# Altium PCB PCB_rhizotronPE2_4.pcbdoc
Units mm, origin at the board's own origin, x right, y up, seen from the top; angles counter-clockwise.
Board outline 108.2 x 57.53 mm, 2 copper layers (Top Layer, Bottom Layer); 76 components, 109 nets, 306 pads, 195 vias.
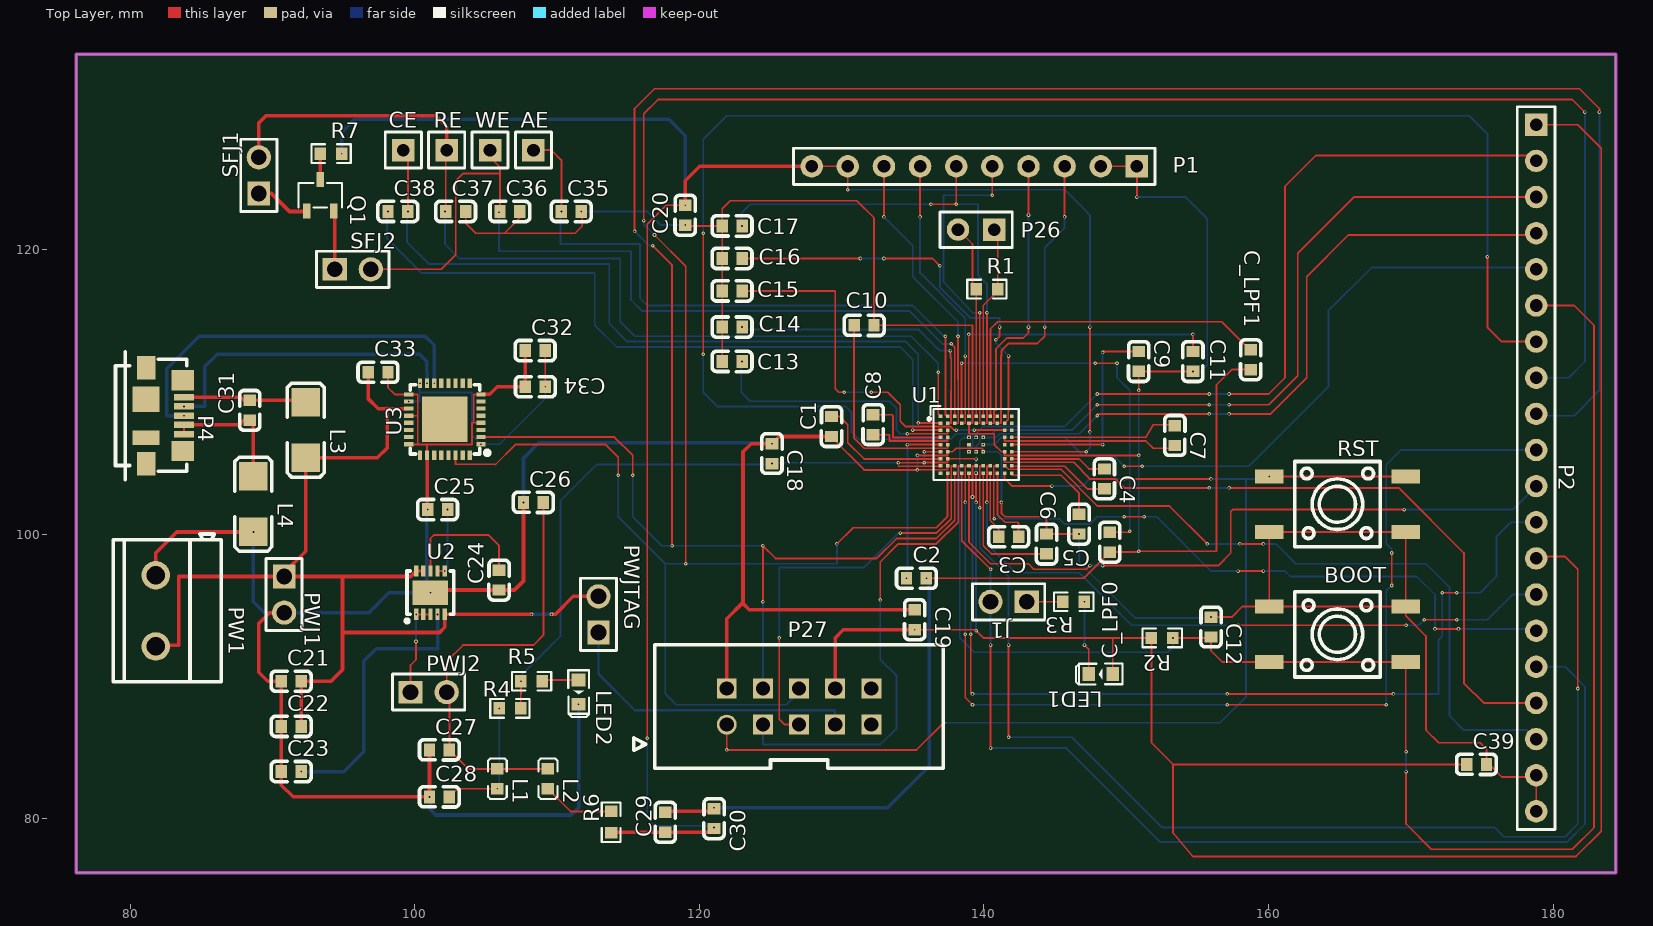
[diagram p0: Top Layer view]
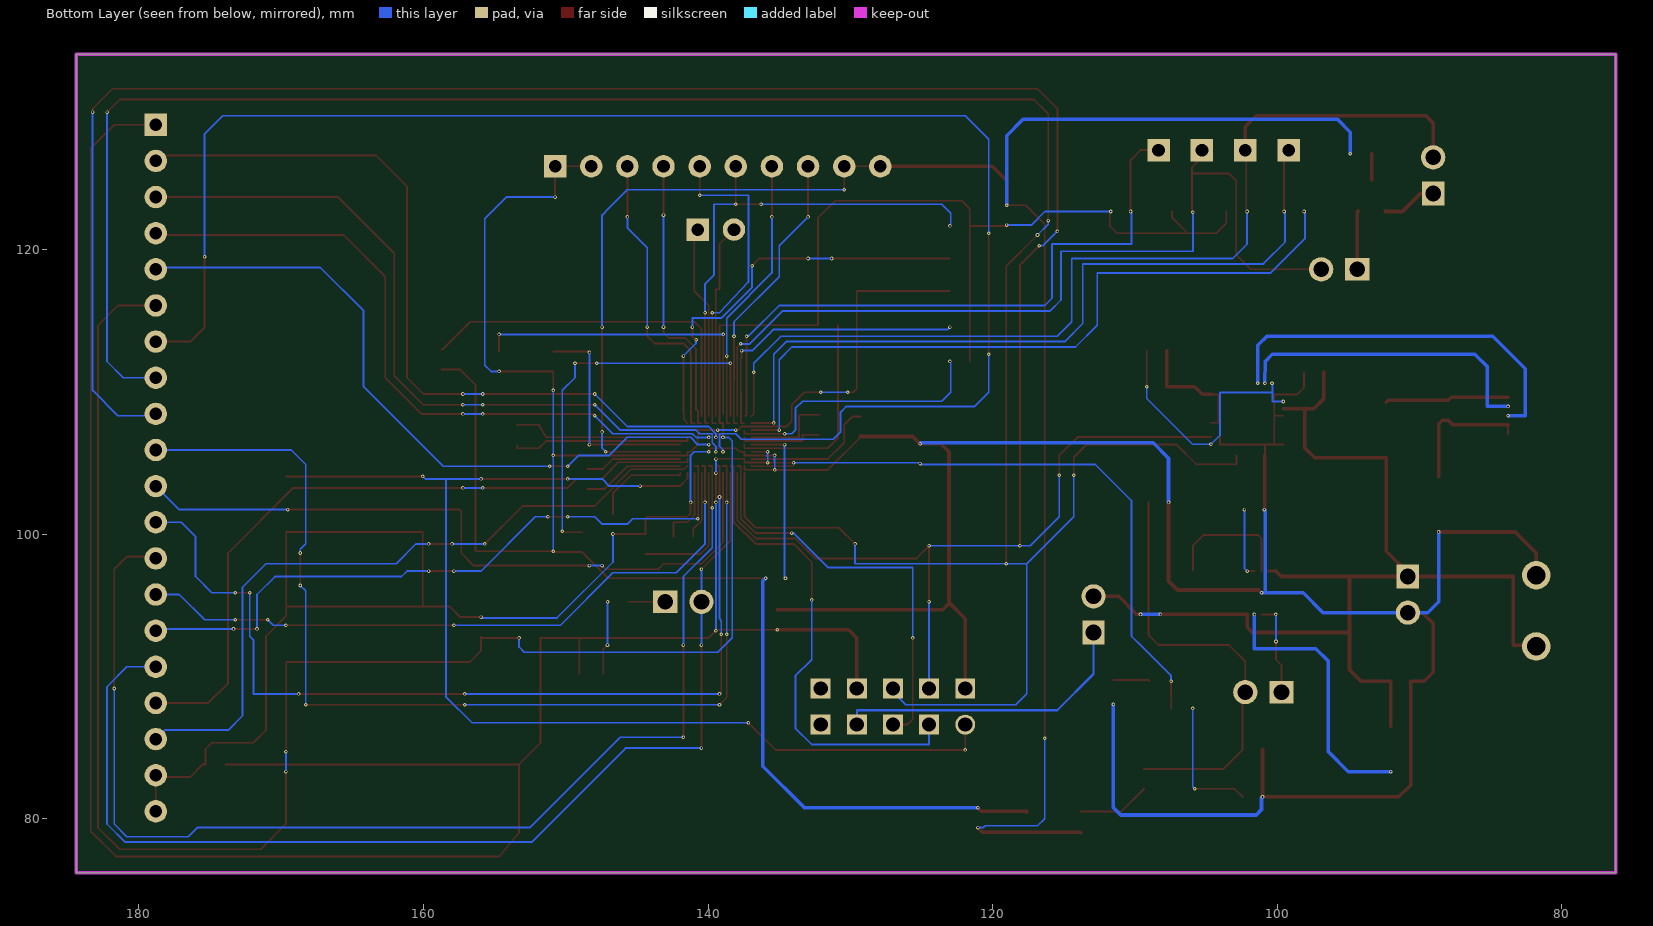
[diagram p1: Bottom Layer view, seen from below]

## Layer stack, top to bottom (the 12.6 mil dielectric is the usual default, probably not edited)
Top Layer: signal copper (thickness not stored)
Dielectric: dielectric 0.32, FR-4, Dk 4.8
Bottom Layer: signal copper (thickness not stored)

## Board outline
79.121,133.731 132.461,133.731 184.404,133.731 184.404,76.2 76.2,76.2 76.2,133.731

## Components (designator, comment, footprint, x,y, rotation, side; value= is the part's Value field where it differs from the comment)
AE "HDR-M-2.54_1x1" HDR-M-2.54_1X1 108.331,127 r270 top
BOOT "K4-6×6_SMD" KEY-SMD_4P-L6.0-W6.0-P3.90-LS10.0 164.846,92.964 r180 top
C1 "0.47uF" C0603 129.286,107.569 r90 top
C2 "0.47uF" C0603 135.255,96.901 r0 top
C3 "0.1uF" C0603 141.732,99.822 r180 top
C4 "0.1uF" C0603 148.463,103.886 r270 top
C5 "0.47uF" C0603 146.685,100.711 r90 top
C6 "0.47uF" C0603 144.399,99.314 r90 top
C7 "0.1uF" C0603 153.416,106.934 r270 top
C8 "0.1uF" C0603 132.207,107.696 r270 top
C9 "0.47uF" C0603 150.876,112.141 r90 top
C10 "0.47uF" C0603 131.572,114.681 r180 top
C11 "4.7uF" C0603 154.686,112.141 r90 top
C12 "0.1uF" C0603 155.956,93.472 r270 top
C13 "0.1uF" C0603 122.301,112.141 r0 top
C14 "0.1uF" C0603 122.301,114.554 r0 top
C15 "0.1uF" C0603 122.301,117.094 r0 top
C16 "0.1uF" C0603 122.301,119.38 r0 top
C17 "0.1uF" C0603 122.301,121.666 r0 top
C18 "0.1uF" C0603 125.095,105.664 r270 top
C19 "0.1uF" C0603 135.128,93.98 r270 top
C20 "0.1uF" C0603 118.999,122.428 r90 top
C21 "0.1uF" C0603 91.313,89.662 r0 top
C22 "10uF" C0603 91.313,86.487 r0 top
C23 "1uF" C0603 91.313,83.312 r0 top
C24 "1uF" C0603 105.918,96.774 r90 top
C25 "1uF" C0603 101.6,101.727 r0 top
C26 "10uF" C0603 108.331,102.235 r0 top
C27 "0.1uF" C0603 101.727,84.836 r0 top
C28 "0.1uF" C0603 101.727,81.534 r0 top
C29 "0.1uF" C0603 117.602,79.756 r90 top
C30 "10uF" C0603 121.031,80.01 r90 top
C31 "0.1uF" C0603 88.392,108.712 r90 top
C32 "0.1uF" C0603 108.458,112.903 r0 top
C33 "0.1uF" C0603 97.409,111.379 r0 top
C34 "0.1uF" C0603 108.458,110.363 r180 top
C35 "0.1uF" C0603 110.998,122.682 r0 top
C36 "0.1uF" C0603 106.68,122.682 r0 top
C37 "0.1uF" C0603 102.87,122.682 r0 top
C38 "0.1uF" C0603 98.806,122.682 r0 top
C39 "0.1uF" C0603 174.625,83.82 r0 top
C_LPF0 "4.7uF" C0603 148.844,99.441 r90 top
C_LPF1 "4.7uF" C0603 158.75,112.268 r90 top
CE "HDR-M-2.54_1x1" HDR-M-2.54_1X1 99.187,127 r270 top
J1 "HDR-M-2.54_1x2" HDR-M-2.54_1X2 141.732,95.25 r180 top
L1 "60Ω" L0603 105.791,82.804 r270 top
L2 "60Ω" L0603 109.347,82.804 r270 top
L3 "80Ω" L1806 92.329,107.315 r270 top
L4 "80Ω" L1806 88.646,102.108 r270 top
LED1 "LED-0603_G" LED0603_GREEN 148.209,90.17 r180 top
LED2 "LED-0603_G" LED0603_GREEN 111.506,88.9 r270 top
P1 "HDR-F-2.54_1x10" HDR-F-2.54_1X10 139.319,125.857 r180 top
P2 "HDR-F-2.54_1x20" HDR-F-2.54_1X20 178.816,104.648 r270 top
P4 "Micro B USB 2.0 SMD connector" SD-47346-001 84.455,108.331 r270 top
P26 "P26" HDR-F-2.54_1X2 139.446,121.412 r180 top
P27 "CONNMOLEX 2X5 Male" JTAG-10PIN-2.54MM-PTH 127,87.884 r0 top
PW1 "CONN-TH_2P-P5.00" CONN-TH_2P-P5.00 81.788,94.615 r270 top
PWJ1 "HDR-M-2.54_1x2" HDR-M-2.54_1X2 90.805,95.758 r270 top
PWJ2 "HDR-M-2.54_1x2" HDR-M-2.54_1X2 100.965,88.9 r0 top
PWJTAG "HDR-M-2.54_1x2" HDR-M-2.54_1X2 112.903,94.361 r90 top
Q1 "MMBFJ177" SOT-23-3_L3.0-W1.7-P0.95-LS2.9-BR 93.345,123.825 r270 top
R1 "200" R0603 140.208,117.221 r0 top
R2 "100K" R0603 152.527,92.71 r180 top
R3 "560" R0603 146.304,95.25 r180 top
R4 "2.2" R0603 106.68,87.757 r180 top
R5 "560" R0603 108.204,89.662 r180 top
R6 "2.2" R0603 113.792,79.756 r90 top
R7 "150K" R0603 94.107,126.746 r0 top
RE "HDR-M-2.54_1x1" HDR-M-2.54_1X1 102.235,127 r270 top
RST "K4-6×6_SMD" KEY-SMD_4P-L6.0-W6.0-P3.90-LS10.0 164.846,102.108 r0 top
SFJ1 "HDR-M-2.54_1x2" HDR-M-2.54_1X2 89.027,125.222 r90 top
SFJ2 "HDR-M-2.54_1x2" HDR-M-2.54_1X2 95.631,118.618 r0 top
U1 "ADUCM355BCCZ" LGA-72_L6.0-W5.0-TL_ADUCM355BCCZ-RL7 139.446,106.299 r0 top
U2 "ADP7158ACPZ-3.3-R7" LFCSP-10_L3.0-W3.0-P0.50-BL-EP 101.092,95.885 r0 top
U3 "FT232RQ" QFN-32_L5.0-W5.0-P0.50-BL-EP 102.108,108.077 r90 top
WE "HDR-M-2.54_1x1" HDR-M-2.54_1X1 105.283,127 r270 top

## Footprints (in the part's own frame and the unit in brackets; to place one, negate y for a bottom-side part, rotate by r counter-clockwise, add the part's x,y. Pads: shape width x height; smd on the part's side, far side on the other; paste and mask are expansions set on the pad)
C0603 [mm]
  rect 0.8x0.9 smd paste+0 mask+0.051: 1(-0.7,0) 2(0.7,0)
  silkscreen extent -1.41,-0.71 1.39,0.72
CONN-TH_2P-P5.00 [mm]
  round 2 hole 1.3 paste+0 mask+0.051: 1(-2.504,0) 2(2.504,0)
  silkscreen extent -5.4,-3 5,4.6
HDR-F-2.54_1X2 [mil]
  rect 62x62 hole 35 paste+0 mask+2: 1(-50,0)
  round 62 hole 35 paste+0 mask+2: 2(50,0)
  silkscreen extent -100,-49 100,50
HDR-F-2.54_1X10 [mil]
  rect 62x62 hole 35 paste+0 mask+2: 1(-450,0)
  round 62 hole 35 paste+0 mask+2: 2(-350,0) 3(-250,0) 4(-150,0) 5(-50,0) 6(50,0) 7(150,0) 8(250,0) 9(350,0) 10(450,0)
  silkscreen extent -500,-50 500,50
HDR-F-2.54_1X20 [mil]
  rect 62x62 hole 35 paste+0 mask+2: 1(-950,0)
  round 62 hole 35 paste+0 mask+2: 2(-850,0) 3(-750,0) 4(-650,0) 5(-550,0) 6(-450,0) 7(-350,0) 8(-250,0) 9(-150,0) 10(-50,0) 11(50,0) 12(150,0) 13(250,0) 14(350,0) 15(450,0) 16(550,0) 17(650,0) 18(750,0) 19(850,0) 20(950,0)
  silkscreen extent -1000,-53 1000,53
HDR-M-2.54_1X1 [mil]
  rect 62x62 hole 35 paste+0 mask+2: 1(0,0)
  silkscreen extent -50,-50 50,50
HDR-M-2.54_1X2 [mm]
  rect 1.7x1.575 hole 1.1 paste+0 mask+0.051: 1(-1.27,0)
  round 1.7 hole 1.1 paste+0 mask+0.051: 2(1.27,0)
  silkscreen extent -2.54,-1.27 2.54,1.27
JTAG-10PIN-2.54MM-PTH [mm]
  round 1.4 hole 1.001 paste+0 mask+0.051: 1(-5.08,-1.27)
  rect 1.4x1.4 hole 1.001 paste+0 mask+0.051: 2(-5.08,1.27) 3(-2.54,-1.27) 4(-2.54,1.27) 5(0,-1.27) 6(0,1.27) 7(2.54,-1.27) 8(2.54,1.27) 9(5.08,-1.27) 10(5.08,1.27)
  silkscreen extent -11.61,-4.34 10.13,4.34
KEY-SMD_4P-L6.0-W6.0-P3.90-LS10.0 [mm]
  rect 2x1 smd paste+0 mask+0.051: 1(-4.8,1.95) 2(4.8,1.95) 3(-4.8,-1.95) 4(4.8,-1.95)
  silkscreen extent -3,-3 3,3
L0603 [mm]
  rect 0.8x0.864 smd paste-100 mask+0.051: 1(-0.7,0) 2(0.7,0)
  silkscreen extent -1.42,-0.65 1.41,0.67
L1806 [mm]
  rect 2x2 smd paste+0 mask+0.051: 1(-1.95,0) 2(1.95,0)
  silkscreen extent -3.3,-1.3 3.3,1.3
LED0603_GREEN [mm]
  rect 0.9x1 smd paste+0 mask+0.051: 1(-0.85,0) 2(0.85,0)
  silkscreen extent -1.54,-0.73 1.75,0.73
LFCSP-10_L3.0-W3.0-P0.50-BL-EP [mm]
  rect 0.3x0.8 smd paste+0 mask+0.051: 1(-1,-1.524) 2(-0.5,-1.524) 3(0,-1.524) 4(0.5,-1.524) 5(1,-1.524) 6(1,1.524) 7(0.5,1.524) 8(0,1.524) 9(-0.5,1.524) 10(-1,1.524)
  rect 2.5x1.75 smd paste+0 mask+0.051: 11(0,0)
  silkscreen extent -1.77,-2.11 1.65,1.52
LGA-72_L6.0-W5.0-TL_ADUCM355BCCZ-RL7 [mm]
  rect 0.25x0.25 smd paste+0 mask+0.051: A1(-2.5,2) A2(-2,2) A3(-1.5,2) A4(-1,2) A5(-0.5,2) A6(0,2) A7(0.5,2) A8(1,2) A9(1.5,2) A10(2,2) A11(2.5,2) B1(-2.5,1.5) B2(-2,1.5) B3(-1.5,1.5) B4(-1,1.5) B5(-0.5,1.5) B6(0,1.5) B7(0.5,1.5) B8(1,1.5) B9(1.5,1.5) B10(2,1.5) B11(2.5,1.5) C1(-2.5,1) C2(-2,1) C10(2,1) C11(2.5,1) D1(-2.5,0.5) D2(-2,0.5) D5(-0.5,0.5) D6(0,0.5) D7(0.5,0.5) D10(2,0.5) D11(2.5,0.5) E1(-2.5,0) E2(-2,0) E5(-0.5,0) E7(0.5,0) E10(2,0) E11(2.5,0) F1(-2.5,-0.5) F2(-2,-0.5) F5(-0.5,-0.5) F6(0,-0.5) F7(0.5,-0.5) F10(2,-0.5) F11(2.5,-0.5) G1(-2.5,-1) G2(-2,-1) G10(2,-1) G11(2.5,-1) H1(-2.5,-1.5) H2(-2,-1.5) H3(-1.5,-1.5) H4(-1,-1.5) H5(-0.5,-1.5) H6(0,-1.5) H7(0.5,-1.5) H8(1,-1.5) H9(1.5,-1.5) H10(2,-1.5) H11(2.5,-1.5) J1(-2.5,-2) J2(-2,-2) J3(-1.5,-2) J4(-1,-2) J5(-0.5,-2) J6(0,-2) J7(0.5,-2) J8(1,-2) J9(1.5,-2) J10(2,-2) J11(2.5,-2)
  silkscreen extent -3.4,-2.5 3,2.7
QFN-32_L5.0-W5.0-P0.50-BL-EP [mil]
  rect 11.8x26 smd paste-3937 mask+1.97: 1(-68.9,-100) 2(-49.21,-100) 3(-29.53,-100) 4(-9.84,-100) 5(9.84,-100) 6(29.53,-100) 7(49.21,-100) 8(68.9,-100) 17(68.9,100) 18(49.21,100) 19(29.53,100) 20(9.84,100) 21(-9.84,100) 22(-29.53,100) 23(-49.21,100) 24(-68.9,100)
  rect 26x11.8 smd paste-3937 mask+1.97: 9(100,-68.9) 10(100,-49.21) 11(100,-29.53) 12(100,-9.84) 13(100,9.84) 14(100,29.53) 15(100,49.21) 16(100,68.9) 25(-100,68.9) 26(-100,49.21) 27(-100,29.53) 28(-100,9.84) 29(-100,-9.84) 30(-100,-29.53) 31(-100,-49.21) 32(-100,-68.9)
  rect 126x126 smd paste-3937 mask+1.97: 33(0,0)
  silkscreen extent -99,-123 96,96
R0603 [mm]
  rect 0.806x0.864 smd paste-100 mask+0.051: 1(-0.753,0) 2(0.753,0)
  silkscreen extent -1.39,-0.66 1.39,0.66
SD-47346-001 [mm]
  rect 0.45x1.38 smd paste+0 mask+0.102: 1(-1.3,-0.69) 2(-0.65,-0.69) 3(0,-0.69) 4(0.65,-0.69) 5(1.3,-0.69)
  rect 1.425x1.55 smd paste+0 mask+0.102: 6(-2.488,-0.775) GND(2.488,-0.775)
  rect 1.65x1.3 smd paste+0 mask+0.102: 7(-3.375,-3.35) 10(3.375,-3.35)
  rect 1.8x1.9 smd paste+0 mask+0.102: 8(-1.15,-3.35)
  rect 1x1.9 smd paste+0 mask+0.102: 9(1.55,-3.35)
  silkscreen extent -4.49,-5.5 4.49,-0.5
SOT-23-3_L3.0-W1.7-P0.95-LS2.9-BR [mm]
  rect 1.037x0.532 smd paste+0 mask+0.051: 1(1.101,-0.95) 2(1.101,0.95) 3(-1.101,0)
  silkscreen extent -0.86,-1.53 0.86,1.53

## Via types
v1: diameter 0.25, hole 0.125, Top Layer to Bottom Layer, tented both sides, 195 vias

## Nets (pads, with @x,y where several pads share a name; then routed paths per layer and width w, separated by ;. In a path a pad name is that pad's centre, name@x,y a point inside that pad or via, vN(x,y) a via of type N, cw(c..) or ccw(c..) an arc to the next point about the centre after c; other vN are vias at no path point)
3V3VOUT: C32.2 C34.1 U3.1 U3.16 U3.18 | length 18.8
  Top Layer w0.125: v1(109.158,110.363) C32.2
  Bottom Layer w0.125: v1(99.568,109.327) 100.33,109.327 100.33,110.589 v1(100.358,110.617) ; 100.33,109.958 104.013,109.958 104.013,106.962 v1(104.648,106.327) 105.946,106.327 109.159,109.54 v1(109.158,110.363)
5VUSB: C21.2 C22.2 C33.1 L3.2 PW1.2 PWJ1.1 PWJTAG.2 U2.5 U2.9 U2.10 U3.19 | length 79.4
  Top Layer w0.225: U2.10 U2.9
  Top Layer w0.254: PW1.2 81.879,92.202 83.403,92.202 83.403,97.028 ; 83.439,97.028 83.403,97.028 ; C22.2 C21.2 94.107,89.662 94.911,90.466 94.911,97.028 ; L3.2 97.363,105.364 98.044,106.045 98.044,108.331 98.044,108.839 U3.19 ; L3.2 92.329,98.806 90.805,97.282 PWJ1.1 ; 94.91,92.837 94.91,93.091 101.727,93.091 102.093,93.457 U2.5 ; C33.1 96.708,109.535 97.419,108.826 98.044,108.826 ; U2.10 99.711,97.028 PWJ1.1 ; U2.5 v1(108.204,94.361) ; v1(109.601,94.361) 109.855,94.361 111.125,95.631 PWJTAG.2 ; 83.403,97.028 PWJ1.1
  Bottom Layer w0.254: v1(108.204,94.361) v1(109.601,94.361)
AFEDIE_GPIO0: P2.17 U1.G10 | length 50
  Top Layer w0.125: U1.G10 141.447,105.059 146.304,105.059 147.447,103.886 149.225,103.886 149.86,103.251 v1(155.829,103.251) ; v1(157.226,103.251) 169.164,103.251 173.736,98.679 173.736,89.535 175.133,88.138 P2.17
  Bottom Layer w0.125: v1(155.829,103.251) v1(157.226,103.251)
AFEDIE_GPIO1: P2.18 U1.H10 | length 50.6
  Top Layer w0.125: U1.H10@141.447,104.798 141.724,104.561 145.415,104.561 147.955,101.981 153.035,101.981 v1(155.702,99.314) ; v1(157.988,99.314) v1(159.639,99.314)
  Bottom Layer w0.125: v1(155.702,99.314) v1(157.988,99.314) ; v1(159.639,99.314) 160.528,99.314 161.925,97.917 171.069,97.917 172.72,96.266 172.72,87.249 173.736,86.233 178.181,86.233 P2.18
AGND: C2.2 C9.1 C10.1 C11.1 C13.1 C14.1 C15.1 C16.1 C17.1 C20.1 C29.2 C30.2 C35.2 C36.2 C37.2 C_LPF0.1 C_LPF1.1 P1.1 P1.2 U1.B5 U1.F10 | length 187.6
  Top Layer w0.125: C37.2 103.57,121.855 104.267,121.158 106.299,121.158 ; C36.2 107.38,122.239 106.299,121.158 ; v1(111.698,122.682) 111.76,122.682 111.76,121.666 111.252,121.158 106.299,121.158 ; v1(118.999,121.728) 119.061,121.666 C17.1 ; C13.1 C14.1 C15.1 C16.1 C17.1 ; C10.1 132.272,122.236 131.064,123.444 122.174,123.444 121.601,122.871 C17.1 ; C10.1 139.192,114.681 139.192,111.445 139.184,107.823 U1.B5@138.938,107.823 ; v1(135.955,96.901) 147.004,96.901 C_LPF0.1 150.811,98.741 v1(150.876,98.806) 156.337,98.806 156.337,110.49 157.415,111.568 C_LPF1.1 ; U1.B5@138.946,107.8 138.946,107.061 140.716,107.061 140.716,106.299 141.232,105.799 U1.F10 141.447,105.537 v1(150.876,105.537) ; P1.2 P1.1 v1(150.749,123.698) ; 150.876,110.236 C9.1 v1(154.686,111.441)
  Top Layer w0.254: C29.2 117.602,80.518 120.777,80.518 v1(121.031,80.772)
  Bottom Layer w0.125: v1(111.698,122.682) 116.332,122.682 117.286,121.728 v1(118.999,121.728) ; v1(150.749,123.698) 154.178,123.698 155.702,122.174 155.702,111.887 155.256,111.441 v1(154.686,111.441) ; v1(150.876,98.806) v1(150.876,105.537) 150.876,110.236
  Bottom Layer w0.254: v1(121.031,80.772) 133.223,80.772 136.144,83.693 136.144,96.712 v1(135.955,96.901)
  other v1: 150.876,110.109
AIN0: P1.3 U1.B9 | length 21.3
  Top Layer w0.125: U1.B9 141.191,107.799 141.191,112.522 ; 141.224,112.522 141.224,112.903 141.732,113.411 143.764,113.411 144.272,113.919 v1(144.272,114.554) ; v1(145.669,122.301) P1.3
  Bottom Layer w0.125: v1(144.272,114.554) 144.272,120.142 145.669,121.539 v1(145.669,122.301)
AIN1: P1.4 U1.B8 | length 20.1
  Top Layer w0.125: U1.B8@140.447,107.8 140.707,107.8 140.707,108.712 140.843,108.712 140.843,112.522 140.843,113.03 141.605,113.792 142.748,113.792 143.129,114.173 v1(143.129,114.554) ; v1(143.129,122.428) P1.4
  Bottom Layer w0.125: v1(143.129,114.554) v1(143.129,122.428)
AIN2: P1.5 U1.B6 | length 23.1
  Top Layer w0.125: U1.B6@139.446,107.8 139.7,107.8 v1(139.7,115.57) ; v1(140.589,123.825) P1.5
  Bottom Layer w0.125: v1(139.7,115.57) 139.192,115.57 137.16,117.729 137.16,123.825 v1(140.589,123.825)
AIN3: C17.2 P1.6 U1.B7 | length 36.4
  Top Layer w0.125: v1(136.271,123.19) v1(138.049,123.19) P1.6 ; U1.B7 140.208,107.799 v1(140.208,115.57)
  Bottom Layer w0.125: v1(123.001,121.666) 122.936,121.666 122.936,122.555 123.571,123.19 v1(136.271,123.19) ; v1(138.049,123.19) 139.573,123.19 139.573,118.237 140.208,117.602 v1(140.208,115.57)
AIN5: P1.7 U1.B4 | length 19.6
  Top Layer w0.125: v1(135.509,122.301) P1.7 ; U1.B4@138.455,107.8 138.684,107.8 v1(138.684,112.522)
  Bottom Layer w0.125: v1(135.509,122.301) 135.509,118.364 138.684,115.189 v1(138.684,112.522)
AIN6: P1.8 U1.B3 | length 20.5
  Top Layer w0.125: v1(132.969,122.301) P1.8 ; U1.B3@137.947,107.8 138.196,107.8 v1(138.176,113.919)
  Bottom Layer w0.125: v1(132.969,122.301) 135.001,120.269 135.001,118.11 138.176,114.935 v1(138.176,113.919)
AVDD: C20.2 C29.1 C30.1 P1.9 P1.10 R6.1 R7.2 U1.F11 | length 143.8
  Top Layer w0.125: v1@116.332,85.598 116.332,121.793 117.667,123.128 v1(118.999,123.128) ; P1.10 P1.9 v1(130.429,124.206) ; U1.F11 141.953,105.791 v1(147.193,105.791) ; v1(147.447,107.188) v1(147.447,114.554)
  Top Layer w0.254: R6.1 113.845,79.056 C29.1 120.712,79.056 v1(121.031,79.375) ; v1(118.999,123.128) 118.999,124.841 120.015,125.857 P1.10
  Bottom Layer w0.125: v1(116.332,85.649) 116.332,80.01 116.84,79.502 120.523,79.502 120.65,79.375 v1(121.031,79.375) ; v1(130.429,124.206) 145.669,124.206 146.977,122.898 147.447,122.428 v1(147.447,114.554) ; v1(147.193,105.791) 147.447,106.045 v1(147.447,107.188)
  Bottom Layer w0.254: v1(94.86,126.746) 94.86,128.261 95.758,129.159 117.856,129.159 118.999,128.016 v1(118.999,123.128)
C23_2: C23.2 U2.4 | length 19.3
  Bottom Layer w0.254: v1(92.013,83.312) 94.996,83.312 96.393,84.709 96.393,91.059 97.282,91.948 101.592,91.948 v1(101.592,94.361)
C24_2: C24.2 U2.8 | length 9.2
  Top Layer w0.125: U2.8 101.092,99.695 101.346,99.949 105.156,99.949 105.918,99.187 C24.2
C25_2: C25.2 U2.6 U2.7 | length 4.9
  Top Layer w0.125: U2.7 v1(102.092,97.409)
  Bottom Layer w0.125: v1(102.092,97.409) 102.3,97.617 v1(102.3,101.727)
CAP_POT0: C38.1 U1.C1 | length 51.5
  Top Layer w0.125: v1(135.001,107.315) 136.93,107.315 U1.C1
  Bottom Layer w0.125: v1(98.106,122.682) 98.044,122.62 98.044,120.777 100.457,118.364 112.649,118.364 112.649,114.681 114.173,113.157 134.112,113.157 135.001,112.268 v1(135.001,107.315)
CAP_POT1: U1.C11
CE0: C38.2 CE.1 U1.B1 | length 54.7
  Top Layer w0.125: CE.1 99.506,126.681 v1(99.506,122.682) ; v1(135.382,107.823) 136.922,107.823 U1.B1
  Bottom Layer w0.125: v1(99.506,122.682) 99.441,122.617 99.441,120.523 100.965,118.999 113.665,118.999 113.665,114.808 114.935,113.538 134.493,113.538 135.382,112.649 v1(135.382,107.823)
CE1: U1.B11
DE0: AE.1 C35.1 U1.A2 | length 45.9
  Top Layer w0.125: AE.1 109.598,127 110.297,126.299 v1(110.297,122.682) ; v1(137.287,113.919) 137.287,108.331 U1.A2@137.414,108.331
  Bottom Layer w0.125: v1(110.297,122.682) 110.236,122.621 110.236,120.396 115.824,120.396 115.824,116.586 116.332,116.078 135.001,116.078 137.16,113.919 v1(137.287,113.919)
DE1: U1.A10
DVDD: C18.2 C19.2 C39.1 LED1.1 P2.1 P27.8 R2.2 R4.1 R5.2 U1.F1 U1.G2 U1.J6 | length 208.9
  Top Layer w0.125: R4.1 v1(107.45,89.662) ; v1(133.985,105.029) v1(135.806,105.029) ; v1(135.128,93.28) 139.384,93.28 v1(139.446,93.218) 139.954,92.71 R2.2 151.774,85.335 153.289,83.82 ; v1@135.806,105.044 137.447,105.044 U1.G2 ; v1(135.81,105.791) U1.F1@136.906,105.791 ; U1.G2 v1(139.446,105.283) ; v1(139.446,102.235) v1(139.446,104.299) ; LED1.1 149.059,92.71 ; C39.1 153.289,83.82 ; P2.1 181.737,128.778 183.388,127.127 183.388,79.121 181.61,77.343 154.686,77.343 153.289,78.994 153.289,83.82
  Top Layer w0.254: P27.8 129.54,92.71 130.11,93.28 v1(135.128,93.28)
  Bottom Layer w0.125: v1(107.45,89.662) 107.45,90.051 109.474,92.075 110.236,92.837 110.236,102.362 112.776,104.902 125.034,104.902 v1(125.095,104.964) ; v1(125.095,104.964) 125.16,105.029 v1(133.985,105.029) ; v1(135.806,105.029) v1(135.81,105.791) ; v1(139.446,93.218) v1(139.446,102.235) ; v1(139.446,104.299) v1(139.446,105.283)
GND: BOOT.3 BOOT.4 C1.1 C5.1 C6.2 C12.1 C18.1 C19.1 C21.1 C22.1 C23.1 C24.1 C25.1 C26.1 C27.1 C28.1 C32.1 C33.2 C34.2 C39.2 L4.2 LED2.2 P2.19 P2.20 P27.2 PW1.1 PWJ1.2 RST.3 RST.4 U1.F2 U1.F7 U1.H2 U2.11 U3.4 U3.8 U3.17 U3.20 U3.24 U3.26 | length 274.2
  Top Layer w0.125: C33.2 98.109,110.298 98.58,109.827 U3.17 100.203,109.827 100.203,108.326 ; U3.24 99.568,106.299 100.203,106.299 ; U3.20 100.198,108.326 100.203,106.299 ; 100.203,106.36 100.203,106.299 ; U3.26 100.858,106.299 ; 104.14,107.827 104.14,109.827 U3.8 ; U3.4 104.013,107.827 104.013,106.299 100.858,106.299 ; C1.1 129.286,106.807 131.572,104.521 v1(135.315,104.521) ; v1(135.315,104.521) 137.446,104.551 U1.H2 ; v1(135.32,105.537) 137.446,105.537 U1.F2 137.787,105.799 138.049,106.045 139.827,106.045 139.946,105.926 v1(139.946,105.799) ; v1(141.224,102.235) 141.224,101.473 141.478,101.219 144.272,101.219 144.399,101.092 C6.2 v1(146.682,100.014) C5.1 ; v1(155.956,94.172) 157.418,94.172 158.16,94.914 BOOT.4 ; C39.2 175.514,83.82 176.403,82.931 178.689,82.931 P2.19 P2.20 ; C39.2 175.326,84.902 174.882,85.344 171.958,85.344 171.069,86.233 171.069,92.837 169.647,94.259 BOOT.3 ; 100.203,106.299 100.858,106.299 ; BOOT.4 RST.3 RST.4 BOOT.3 ; BOOT.4 BOOT.3
  Top Layer w0.254: PW1.1 81.788,98.679 83.266,100.157 v1(88.646,100.158) ; C23.1 90.612,82.362 91.44,81.534 v1(101.027,81.534) ; C23.1 C22.1 C21.1 89.662,89.662 89.027,90.297 89.027,93.726 89.789,94.488 PWJ1.2 ; U3.26 100.858,101.727 v1(100.9,101.727) ; v1(101.027,81.534) C27.1 ; v1(101.092,95.885) 101.281,96.074 C24.1 106.996,96.074 107.631,96.709 v1(107.631,102.235) ; U3.8 105.255,109.827 105.791,110.363 C34.2 C32.1 ; P27.2 121.92,94.049 123.063,95.192 ; v1(125.095,106.365) 125.6,106.869 C1.1 ; v1(125.095,106.365) 123.637,106.365 123.063,105.791 123.063,95.123 123.505,94.681 C19.1
  Bottom Layer w0.125: v1(135.315,104.521) v1(135.32,105.537) ; v1(139.946,105.799) 140.962,105.799 141.224,105.537 v1(141.224,102.235) ; v1(146.682,100.014) 146.682,98.047 150.622,94.107 155.891,94.107 v1(155.956,94.172)
  Bottom Layer w0.254: v1(88.646,100.158) 88.646,95.25 89.408,94.488 PWJ1.2 96.774,94.488 98.171,95.885 v1(101.092,95.885) 100.838,95.885 100.838,101.666 v1(100.9,101.727) ; v1(101.027,81.534) 101.092,81.469 101.092,80.645 101.473,80.264 110.998,80.264 111.506,80.772 v1(111.506,88.05) ; v1(107.631,102.235) 107.631,105.345 108.712,106.426 125.034,106.426 v1(125.095,106.365)
L1_2: C28.2 L1.2 R4.2 | length 9.3
  Top Layer w0.125: C28.2 102.997,82.104 v1(105.791,82.104)
  Bottom Layer w0.125: v1(105.791,82.104) 105.927,82.24 v1(105.927,87.757)
L2_2: L2.2 R6.2 | length 5.1
  Top Layer w0.125: L2.2 110.942,80.509 R6.2
LED1_2: LED1.2 R3.1 | length 5.2
  Top Layer w0.125: v1(147.066,92.202) 147.359,91.909 LED1.2
  Bottom Layer w0.125: v1(147.057,95.25) v1(147.066,92.202)
P0.0_SCLK0: P2.15 U1.H9 | length 47.2
  Top Layer w0.125: v1@140.693,101.092 140.693,104.798 U1.H9@140.947,104.798 ; v1(149.86,101.219) v1(151.257,101.219) ; v1(157.861,97.409) v1(159.639,97.409) ; v1(171.704,93.345) v1(173.355,93.345)
  Bottom Layer w0.125: v1(140.716,101.092) 145.288,101.092 145.669,100.711 147.447,100.711 147.955,101.219 v1(149.86,101.219) ; v1(151.257,101.219) 152.146,101.219 155.956,97.409 v1(157.861,97.409) ; v1(159.639,97.409) 161.163,97.409 161.544,97.028 170.434,97.028 171.704,95.758 v1(171.704,93.345) ; v1(173.355,93.345) 178.689,93.345 P2.15
P0.1_MOSI0: P2.14 U1.H8 | length 50
  Top Layer w0.125: 140.208,104.648 v1(140.208,102.235) 140.208,104.798 U1.H8@140.447,104.798 ; v1(157.861,93.599) v1(169.672,93.599) ; v1(170.942,93.98) v1(173.228,93.98)
  Bottom Layer w0.125: v1(140.208,102.235) 140.208,99.314 142.24,97.282 146.685,97.282 150.368,93.599 v1(157.861,93.599) ; v1(169.672,93.599) 170.561,93.599 v1(170.942,93.98) ; v1(173.228,93.98) 175.387,93.98 177.165,95.758 P2.14
P0.2_MISO0: P2.13 U1.H7 | length 84.7
  Top Layer w0.125: v1(139.7,101.854) 139.7,104.798 U1.H7@139.946,104.798 ; v1(141.732,85.725) v1(141.732,92.202) ; P2.13 178.943,98.425 180.848,98.425 181.737,97.536 v1(181.737,89.154)
  Bottom Layer w0.125: v1(139.7,101.854) 139.7,99.06 141.732,97.028 v1(141.732,92.202) ; v1(141.732,85.725) 146.177,85.725 152.527,79.375 175.895,79.375 176.53,78.74 180.848,78.74 181.737,79.629 v1(181.737,89.154)
P0.3_CS0: P2.12 U1.H6 | length 66.6
  Top Layer w0.125: v1(139.065,92.964) 139.065,88.9 v1(139.192,88.773) ; v1(139.192,102.616) 139.192,104.625 139.192,104.798 U1.H6@139.446,104.798 ; v1(157.099,88.773) v1(168.783,88.773) ; v1(172.212,95.885) v1(173.228,95.885)
  Bottom Layer w0.125: v1(139.065,92.964) 139.065,93.853 139.192,94.107 v1(139.192,102.616) ; v1(139.192,88.773) v1(157.099,88.773) ; v1(168.783,88.773) 171.958,88.773 171.958,92.583 172.212,92.837 v1(172.212,95.885) ; v1(173.228,95.885) 174.879,95.885 176.022,97.028 176.022,99.822 177.038,100.838 P2.12
P0.4_SCL: P2.11 U1.J5 | length 49.7
  Top Layer w0.125: U1.J5 138.946,99.433 140.462,97.917 143.129,97.917 143.51,97.536 147.193,97.536 v1(147.447,97.79) ; v1(148.336,97.79) 156.464,97.79 157.353,98.679 157.353,101.6 157.48,101.727 v1(169.545,101.727)
  Bottom Layer w0.125: v1(147.447,97.79) v1(148.336,97.79) ; v1(169.545,101.727) 177.165,101.727 P2.11
P0.5_SDA: P2.10 U1.H5 | length 74.5
  Top Layer w0.125: v1(138.684,92.964) 138.684,88.519 v1(139.192,88.011) ; v1@138.684,102.235 138.684,104.798 U1.H5@138.946,104.798 ; v1(157.099,88.011) v1(168.275,88.011) ; v1(168.656,96.393) v1(168.656,98.679)
  Bottom Layer w0.125: v1(138.684,92.964) v1@138.684,102.235 ; v1(139.192,88.011) v1(157.099,88.011) ; v1(168.275,88.011) 168.275,96.012 v1(168.656,96.393) ; v1(168.656,98.679) 168.656,98.933 168.275,99.314 168.275,104.902 169.291,105.918 P2.10
  other v1: 138.694,102.235
P0.10_SOUT: P2.9 P27.4 U1.J3 U3.2 | length 179.8
  Top Layer w0.125: U3.2 114.026,106.827 115.316,105.537 v1(115.316,104.14) ; v1(115.443,121.285) 115.443,129.921 116.84,131.318 181.864,131.318 183.261,129.921 v1(183.261,129.667) ; v1(116.713,120.269) 118.081,118.901 v1(118.081,99.187) ; v1(124.46,95.25) v1(124.46,99.187) 125.349,98.298 132.461,98.298 133.858,99.695 136.652,99.695 137.945,100.988 U1.J3
  Bottom Layer w0.125: v1(115.316,104.14) 115.316,101.219 117.348,99.187 v1(118.081,99.187) v1(124.46,99.187) ; v1(115.443,121.285) 116.459,120.269 v1(116.713,120.269) ; P27.4 v1(124.46,95.25) ; P2.9 178.943,108.331 181.483,108.331 183.261,110.109 v1(183.261,129.667)
P0.11_SIN: P2.8 P27.6 U1.J2 U3.30 | length 187.7
  Top Layer w0.125: U3.30 102.857,104.915 105.664,104.902 107.061,106.299 113.411,106.299 114.3,105.41 v1(114.3,104.14) ; v1(116.078,122.047) 116.078,129.54 117.094,130.556 181.356,130.556 v1(182.245,129.667) ; v1(116.84,121.031) 119.044,118.827 v1(119.044,97.917) ; v1(129.667,99.314) 130.81,100.457 136.652,100.457 137.446,101.251 U1.J2
  Bottom Layer w0.125: v1(114.3,104.14) 114.3,101.219 117.602,97.917 ; v1(116.078,122.047) 116.078,121.793 v1(116.84,121.031) ; P27.6 127,88.9 126.111,88.011 118.364,88.011 117.602,88.773 117.602,97.917 ; v1(129.667,99.314) 129.667,97.917 v1(119.044,97.917) 117.602,97.917 ; P2.8 181.102,110.998 182.245,112.141 v1(182.245,129.667)
P1.0: P2.7 U1.F5 | length 114.2
  Top Layer w0.125: v1(120.269,112.649) v1(120.269,121.158) ; v1(175.387,119.507) 175.387,114.554 176.403,113.538 P2.7
  Bottom Layer w0.125: v1(120.269,112.649) 120.269,109.982 121.285,108.966 130.302,108.966 130.683,108.585 130.683,107.188 131.191,106.68 137.668,106.68 138.049,107.061 139.192,107.061 139.192,106.172 138.946,105.926 v1(138.946,105.799) ; v1(120.269,121.158) 120.269,127.762 121.92,129.413 174.117,129.413 175.387,128.143 v1(175.387,119.507)
P1.1: BOOT.1 BOOT.2 C12.2 P2.6 R2.1 U1.D5 | length 114.4
  Top Layer w0.125: v1(153.28,92.71) 155.894,92.71 C12.2 155.956,91.821 156.763,91.014 BOOT.2 BOOT.1 169.646,84.735 v1(169.672,84.709) ; v1(169.672,83.312) 169.672,79.629 171.45,77.851 181.356,77.851 182.88,79.375 182.88,114.681 181.483,116.078 P2.6
  Bottom Layer w0.125: v1(138.946,106.799) 138.549,106.799 138.303,106.553 138.303,92.71 139.319,91.694 152.908,91.694 153.281,92.067 v1(153.28,92.71) ; v1(169.672,83.312) v1(169.672,84.709)
P1.2_SCLK1: P2.5 U1.E7 | length 48.9
  Top Layer w0.125: v1(149.86,104.775) v1(151.13,104.775)
  Bottom Layer w0.125: v1(139.946,106.299) 140.716,106.299 141.224,106.807 145.669,106.807 146.939,105.537 149.098,105.537 v1(149.86,104.775) ; v1(151.13,104.775) 158.623,104.775 164.211,110.363 164.211,115.697 167.259,118.745 178.689,118.745 P2.5
P1.3_MOSI1: P2.4 U1.D7 | length 49.1
  Top Layer w0.125: v1(147.955,108.331) 147.955,108.458 v1(155.829,108.458) ; v1(157.226,108.458) 160.147,108.458 162.687,110.998 162.687,118.11 165.608,121.031 178.689,121.031 P2.4
  Bottom Layer w0.125: v1(139.946,106.799) 140.835,106.799 141.097,107.061 146.685,107.061 v1(147.955,108.331) ; v1(155.829,108.458) v1(157.226,108.458)
P1.4_MISO1: P2.3 U1.F6 | length 52.4
  Top Layer w0.125: v1(147.955,109.093) v1(155.829,109.093) ; v1(157.226,109.093) 160.02,109.093 162.052,111.125 162.052,119.761 165.989,123.698 P2.3
  Bottom Layer w0.125: v1(139.446,105.791) 139.446,106.172 139.7,106.426 139.7,107.061 140.589,107.061 140.843,107.315 146.177,107.315 v1(147.955,109.093) ; v1(155.829,109.093) v1(157.226,109.093)
P1.5_CS: P2.2 U1.D6 | length 55.8
  Top Layer w0.125: v1(147.955,109.855) v1(155.829,109.855) ; v1(157.226,109.855) 160.02,109.855 161.163,110.998 161.163,124.46 163.322,126.619 178.435,126.619 P2.2
  Bottom Layer w0.125: v1(139.446,106.799) 139.446,107.061 139.954,107.569 145.669,107.569 v1(147.955,109.855) ; v1(155.829,109.855) v1(157.226,109.855)
P2.4: J1.2 P2.16 U1.J4 | length 78.9
  Top Layer w0.125: U1.J4 138.445,99.553 v1(140.462,97.536) ; v1(140.462,84.963) v1(140.462,92.202)
  Bottom Layer w0.125: v1(140.462,84.963) 145.796,84.963 152.4,78.359 180.975,78.359 182.245,79.629 182.245,89.281 180.848,90.678 P2.16 ; v1(140.462,92.202) J1.2 v1(140.462,97.536)
P4_1: C31.2 L3.1 P4.1 | length 8.7
  Top Layer w0.254: P4.1 87.757,109.631 87.976,109.412 C31.2 92.182,109.412 L3.1
P4_4: C31.1 L4.1 P4.4 P4.5 | length 9.5
  Top Layer w0.125: P4.5 P4.4
  Top Layer w0.254: P4.4 87.63,107.681 87.961,108.012 C31.1 88.646,107.758 L4.1
P27_9: P27.9
P27_10: P27.10
PWJ2_2: C26.2 C27.2 L1.1 L2.1 PWJ2.2 | length 30.7
  Top Layer w0.125: C26.2 109.032,92.898 108.334,92.202 103.378,92.202 102.235,91.059 PWJ2.2 102.427,88.708 C27.2 103.759,83.504 L1.1 L2.1
PWJTAG_1: P27.7 PWJTAG.1 | length 21.6
  Bottom Layer w0.152: PWJTAG.1 112.903,90.17 115.443,87.63 129.54,87.63 P27.7
Q1_1: Q1.1 SFJ1.1 | length 3.9
  Top Layer w0.254: SFJ1.1 89.916,123.952 91.186,122.682 92.395,122.682 Q1.1
Q1_2: Q1.2 SFJ2.1 | length 4.1
  Top Layer w0.254: Q1.2 94.361,122.658 SFJ2.1
Q1_3: Q1.3 R7.1 | length 1.8
  Top Layer w0.254: Q1.3 R7.1
R3_2: J1.1 R3.2 | length 2.5
  Top Layer w0.125: J1.1 R3.2
R5_1: LED2.1 R5.1 | length 2.6
  Top Layer w0.125: R5.1 109.045,89.75 LED2.1
RE0: C37.1 RE.1 SFJ1.2 U1.A1 | length 69
  Top Layer w0.125: C37.1 102.17,126.935 RE.1 ; v1(136.779,111.379) 136.779,108.466 U1.A1
  Top Layer w0.254: SFJ1.2 89.027,128.905 89.535,129.413 101.473,129.413 102.235,128.651 RE.1
  Bottom Layer w0.125: v1(102.108,122.682) 102.108,120.396 103.124,119.38 114.427,119.38 114.427,114.935 115.443,113.919 134.874,113.919 136.779,112.014 v1(136.779,111.379)
RE1: U1.A11
RESET: P27.1 RST.1 RST.2 U1.J10 | length 84.2
  Top Layer w0.125: P27.1 v1(121.92,84.836) 135.255,84.836 v1(137.16,86.741) ; U1.J10 141.446,103.918 141.986,103.378 v1(144.78,103.378) ; v1(149.86,103.886) v1(155.956,103.886) ; v1(160.046,104.058) RST.2
  Bottom Layer w0.125: v1(137.16,86.741) 156.591,86.741 158.427,88.577 158.427,103.886 ; v1(144.78,103.378) 146.939,103.378 147.447,103.886 v1(149.86,103.886) ; v1(155.956,103.886) 159.874,103.886 v1(160.046,104.058)
SE0: C36.1 SFJ2.2 U1.A3 WE.1 | length 64
  Top Layer w0.125: SFJ2.2 101.854,118.618 102.87,119.634 102.87,124.841 103.388,125.359 105.979,125.359 ; WE.1 105.283,126.492 105.98,125.795 C36.1 ; v1(137.7,113.379) 137.946,113.133 U1.A3
  Bottom Layer w0.125: v1@105.918,122.682 105.918,119.888 115.189,119.888 115.189,116.459 115.951,115.697 134.747,115.697 137.066,113.378 v1@137.701,113.378
  other v1: 105.918,122.629
SE1: U1.A9
SWCLK: P27.5 U1.H3 | length 29.7
  Top Layer w0.125: v1(125.603,92.71) 125.603,86.995 125.984,86.614 P27.5 ; v1(134.112,100.076) 136.652,100.076 137.698,101.092 137.698,104.798 U1.H3@137.947,104.798
  Bottom Layer w0.125: v1(125.603,92.71) 125.603,97.663 131.572,97.663 133.985,100.076 v1(134.112,100.076)
SWDIO: P27.3 U1.H4 | length 34.3
  Top Layer w0.125: v1(132.715,95.377) 132.715,98.044 133.985,99.314 136.652,99.314 138.186,100.838 138.186,104.798 U1.H4@138.445,104.798
  Bottom Layer w0.125: P27.3 124.46,85.217 132.715,85.217 133.858,86.36 133.858,90.043 132.715,91.186 v1(132.715,95.377)
U1_A4: C_LPF0.2 U1.A4 | length 28.2
  Top Layer w0.125: U1.A4@138.43,108.299 v1(138.43,112.014) ; v1(147.828,112.014) v1(149.352,112.014) ; C_LPF0.2 150.179,100.141 v1(150.241,100.203)
  Bottom Layer w0.125: v1(138.43,112.014) v1(147.828,112.014) ; v1(149.352,112.014) 149.352,110.998 150.241,110.109 v1(150.241,100.203)
U1_A5: C11.2 U1.A5 | length 22.4
  Top Layer w0.125: 138.938,108.458 v1(138.938,114.046) ; C11.2 v1(154.686,114.046)
  Bottom Layer w0.125: v1(138.938,114.046) 154.559,114.046
U1_A6: P26.2 R1.1 U1.A6 | length 13.8
  Top Layer w0.125: P26.2 139.192,120.396 139.192,117.221 R1.1 ; U1.A6@139.455,108.299 R1.1
U1_A7: P26.1 R1.2 U1.A7 | length 13.6
  Top Layer w0.125: U1.A7@139.954,108.299 139.954,116.078 140.961,117.085 R1.2 140.961,121.167 P26.1
U1_A8: C_LPF1.2 U1.A8 | length 25.4
  Top Layer w0.125: U1.A8@140.462,108.299 140.462,114.427 140.97,114.935 156.718,114.935 158.685,112.968 C_LPF1.2
U1_D1: C8.1 U1.D1 | length 6.3
  Top Layer w0.125: C8.1 133.542,108.396 133.604,108.331 133.604,106.799 U1.D1
U1_D2: C8.2 U1.D2 | length 5.9
  Top Layer w0.125: C8.2 133.35,106.996 133.35,106.553 137.446,106.553 U1.D2
U1_D10: C7.2 U1.D10 | length 12.6
  Top Layer w0.125: U1.D10 141.447,106.553 151.384,106.553 151.892,106.045 153.416,106.045 C7.2
U1_D11: C7.1 U1.D11 | length 12
  Top Layer w0.125: U1.D11@141.945,106.807 151.384,106.807 151.892,107.696 153.416,107.696 C7.1
U1_E1: C2.1 U1.E1 | length 11.8
  Top Layer w0.125: v1(134.62,106.299) U1.E1
  Bottom Layer w0.125: v1(134.555,96.901) 134.62,96.966 v1(134.62,106.299)
U1_E2: C10.2 U1.E2 | length 15.1
  Top Layer w0.125: C10.2 130.872,106.745 131.572,106.045 134.554,106.045 137.447,106.045 U1.E2
U1_E5: U1.E5
U1_E10: U1.E10
U1_E11: C9.2 U1.E11 | length 15.4
  Top Layer w0.125: U1.E11 v1(148.336,106.299) ; v1(148.336,112.776) 148.401,112.841 C9.2
  Bottom Layer w0.125: v1(148.336,106.299) v1(148.336,112.776)
U1_G1: C1.2 U1.G1 | length 9.6
  Top Layer w0.125: C1.2 129.856,108.269 130.429,107.696 130.429,106.426 131.572,105.283 U1.G1@136.947,105.283
U1_G11: C4.1 U1.G11 | length 6.8
  Top Layer w0.125: U1.G11@141.946,105.283 146.685,105.283 147.382,104.586 C4.1
U1_H11: C4.2 U1.H11 | length 7.2
  Top Layer w0.125: U1.H11@141.946,104.775 145.669,104.775 147.258,103.186 C4.2
U1_J7: C6.1 U1.J7 | length 9.8
  Top Layer w0.125: U1.J7 139.946,99.195 140.527,98.614 C6.1
U1_J8: C3.2 U1.J8 | length 4.7
  Top Layer w0.125: U1.J8 140.446,100.965 141.032,100.379 C3.2
U1_J9: C3.1 U1.J9 | length 5.6
  Top Layer w0.125: U1.J9 140.947,101.369 141.478,100.838 142.367,100.838 142.433,100.772 C3.1
U1_J11: C5.2 U1.J11 | length 6.9
  Top Layer w0.125: U1.J11 141.945,104.14 145.415,104.14 146.685,102.87 C5.2
U2_1: PWJ2.1 U2.1 U2.2 U2.3 | length 6.6
  Top Layer w0.125: PWJ2.1 99.695,90.805 100.076,91.186 v1(100.076,92.456) ; v1(100.092,94.361) U2.2 U2.3
  Bottom Layer w0.125: v1(100.076,92.456) 100.076,94.345 v1(100.092,94.361)
U3_3: U3.3
U3_5: U3.5
U3_6: U3.6
U3_7: U3.7
U3_9: U3.9
U3_10: U3.10
U3_11: U3.11
U3_12: U3.12
U3_13: U3.13
U3_21: U3.21
U3_22: U3.22
U3_23: U3.23
U3_25: U3.25
U3_27: U3.27
U3_28: U3.28
U3_29: U3.29
U3_31: U3.31
U3_32: U3.32
U3_33: U3.33
USBD+: P4.3 U3.14 | length 27.2
  Bottom Layer w0.254: v1(83.765,108.331) 82.55,108.331 82.55,111.633 84.836,113.919 100.711,113.919 101.358,113.272 v1(101.358,110.617)
  other v1: 101.358,110.617
USBD-: P4.2 U3.15 | length 22
  Bottom Layer w0.254: v1(83.765,108.981) 85.217,108.981 85.217,111.76 86.106,112.649 100.33,112.649 100.838,112.141 v1(100.858,110.617)
VBIAS0: C13.2 U1.C2 | length 19
  Top Layer w0.125: v1(134.62,107.061) 137.447,107.061 U1.C2
  Bottom Layer w0.125: v1(123.001,112.141) 122.936,112.076 122.936,109.982 123.571,109.347 133.35,109.347 133.858,108.839 133.858,107.315 134.112,107.061 v1(134.62,107.061)
VBIAS1: C15.2 U1.C10 | length 27.2
  Top Layer w0.125: C15.2 129.54,117.094 129.54,110.236 129.794,109.982 v1(130.175,109.982) ; v1(132.08,109.982) 133.223,109.982 134.112,109.093 134.112,107.95 134.493,107.561 137.668,107.561 137.922,107.315 v1(138.049,107.315) ; v1(139.319,107.315) U1.C10@141.448,107.315
  Bottom Layer w0.125: v1(130.175,109.982) v1(132.08,109.982) ; v1(138.049,107.315) v1(139.319,107.315)
VZERO0: C14.2 U1.B2 | length 20.7
  Top Layer w0.125: U1.B2 137.688,107.798 137.693,112.395 ; 137.638,112.395 v1(137.638,112.903)
  Bottom Layer w0.125: v1(123.001,114.554) 123.174,114.381 135.428,114.381 136.906,112.903 v1@137.668,112.903
VZERO1: C16.2 U1.B10 | length 28.7
  Top Layer w0.125: C16.2 v1(131.318,119.38) ; v1(132.969,119.38) 136.398,119.38 v1(136.906,118.872) ; v1(140.843,113.665) 141.097,113.919 v1(141.097,114.554) ; U1.B10@141.478,107.823 141.703,108.077 141.703,108.625 ; 141.732,108.625 141.732,112.545 v1@141.763,112.545
  Bottom Layer w0.125: v1(131.318,119.38) v1(132.969,119.38) ; v1(136.906,118.872) 136.906,117.348 139.065,115.189 141.097,115.189 v1(141.097,114.554) ; v1(140.843,113.665) 140.843,113.411 v1(141.732,112.522)
XTALI: U1.H1 | length 3
  Top Layer w0.125: 133.985,104.775 U1.H1
XTALO: U1.J1
"": P4.6 P4.7 P4.8 P4.9 P4.10 P4.GND

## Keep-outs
Board Outline Layer:
  the board outline again, w0.254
